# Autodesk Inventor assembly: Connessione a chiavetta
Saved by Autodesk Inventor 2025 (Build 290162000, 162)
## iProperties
Created: 2025-03
Part Number: Connessione a chiavetta
Document SubType Name: Assembly
Designer: R5800u
ClientObjectVersion: 1
Author: R5800u
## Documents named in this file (1)
- C:\Users\R5800u\Desktop\turgo\Assieme_turgo\Design Accelerator\Connessione a chiavetta2.iam
